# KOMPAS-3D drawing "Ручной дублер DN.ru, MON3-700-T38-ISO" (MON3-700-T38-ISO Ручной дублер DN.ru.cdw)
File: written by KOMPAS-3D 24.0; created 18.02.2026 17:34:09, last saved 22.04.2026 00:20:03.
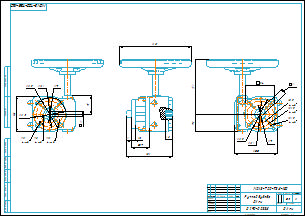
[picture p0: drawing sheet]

Document properties: Автор: R2D2; Форматы листов документа: A2; Полное имя файла: MON3-700-T38-ISO Ручной дублер DN.ru.m3d; Масса: 6.9; Наименование: Ручной дублер DN.ru; Количество листов документа: 1; Примечание: D290-00338

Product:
- Part/product: Ручной дублер DN.ru  | designation MON3-700-T38-ISO
    Масса: 6.9
    Раздел спецификации: Прочие изделия
    Примечание: D290-00338

Views: Вид 1, Спереди, Проекционный вид 2, Местный разрез 1, Проекционный вид 3
Referenced files in E:\Работа\Зайцев\Аксессуары для пневмоприводов\Ручной дублер DN.ru\MON3-700-T38-ISO Ручной дублер DN.ru\: MON3-700-T38-ISO Ручной дублер DN.ru.m3d
Referenced files in E:\Работа\Зайцев\Для компаса\: чертеж DN.ru А3.cdt
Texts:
  Диаметральный размер
  MON3-700-T38-ISO
  чертеж DN.ru А3.cdt
  Ручной дублер
  Ручной дублер DN.ru
  MON3-700-T38-ISO Ручной дублер DN.ru
Dimensions and other numbers on the sheet: 0; 3; 2; 4; 125; 70; 102; 140; 129; 22; 71; 12; 4 отв.; 10; 8; 280; 28; 13; 68,7; 180; 212; 114; 12,5; 10,5; 8,5; 166; 1:2; 1; 6,9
